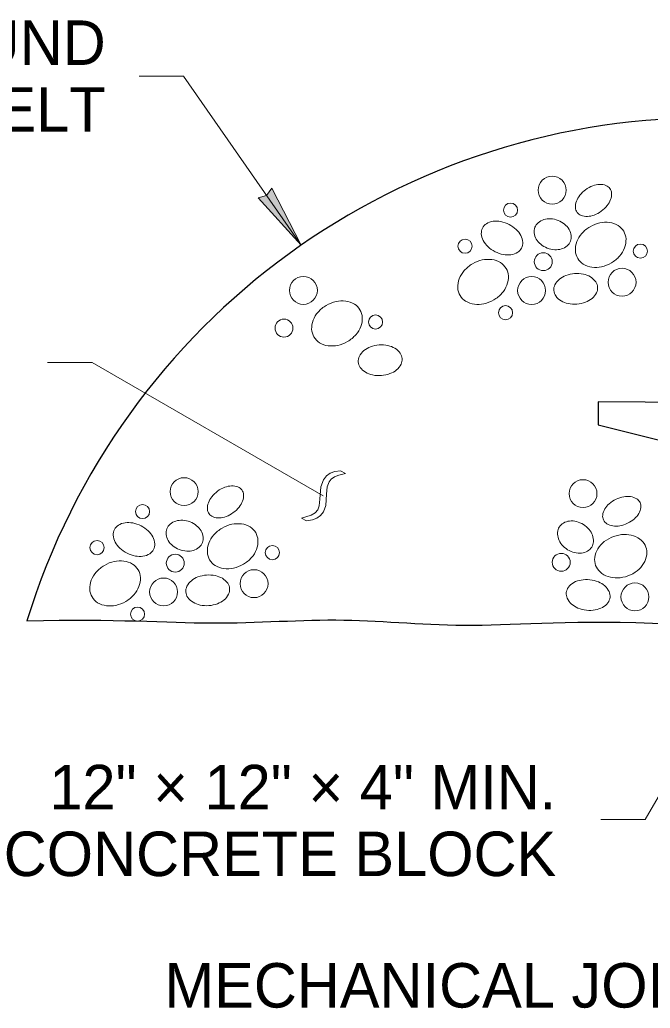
# Model space of a CAD drawing. Extents: x 99860 to 103153, y 99998 to 102077.
# Drawn here: x 100086.3 to 100312.8, y 100201.4 to 100556.8 of the extents above; entities that cross this region are included whole.
import ezdxf
from ezdxf.enums import TextEntityAlignment as Align

# ---------------------------------------------------------------- set-up
doc = ezdxf.new("R2010")
doc.units = 0
doc.header["$LTSCALE"] = 6.4
for name, color, linetype, lineweight in [('1', 7, 'Continuous', 25), ('10', 7, 'Continuous', 13), ('15', 7, 'Continuous', 13), ('18', 7, 'Continuous', 13), ('20', 7, 'Continuous', 13)]:
    doc.layers.add(name, color=color, linetype=linetype, lineweight=lineweight)

msp = doc.modelspace()

# ---------------------------------------------------------------- hatches: boundary and pattern name
at = {"layer": '15'}
msp.add_hatch(color=256, dxfattribs=at).paths.add_polyline_path([(100187.44, 100475.801), (100176.86, 100496.25), (100175.012, 100493.679), (100171.958, 100492.843)])

# ---------------------------------------------------------------- linework, layer by layer
at = {"layer": '1'}
msp.add_arc((100333.435, 100265.78), 255.78, 89.03164, 162.96913, dxfattribs=at)
msp.add_open_spline([(100088.82, 100340.697), (100121.57, 100341.522), (100155.857, 100338.56), (100203.47, 100342.572), (100246.832, 100337.272), (100285.407, 100341.247), (100319.945, 100339.647)], degree=3, dxfattribs=at)
at = {"layer": '10'}
for centre, radius in [((100277.595, 100495.571), 5.019), ((100262.646, 100488.395), 2.537), ((100246.301, 100475.439), 2.537), ((100309.289, 100473.645), 2.537), ((100274.406, 100469.858), 3.22), ((100302.711, 100462.483), 5.019), ((100188.216, 100459.533), 5.019), ((100270.22, 100459.493), 5.019), ((100214.129, 100448.171), 2.537), ((100260.852, 100451.52), 2.537), ((100181.24, 100445.979), 3.22), ((100145.361, 100387.177), 5.019), ((100288.686, 100386.459), 5.019), ((100130.411, 100380.002), 2.537), ((100114.066, 100367.045), 2.537), ((100177.054, 100365.251), 2.537), ((100142.171, 100361.464), 3.22), ((100280.856, 100361.761), 3.22), ((100170.476, 100354.089), 5.019), ((100137.985, 100351.099), 5.019), ((100307.338, 100349.341), 5.019), ((100128.617, 100343.126), 2.537)]:
    msp.add_circle(centre, radius, dxfattribs=at)
for centre, radius, start, end in [((100296.119, 100486.842), 11.024, 110.84431, 126.08477), ((100294.986, 100489.819), 7.839, 92.74951, 110.84431), ((100294.875, 100492.14), 5.515, 68.28483, 92.74951), ((100295.724, 100494.273), 3.219, 36.08477, 68.28483), ((100293.633, 100488.833), 7.839, 141.32523, 159.42002), ((100296.119, 100486.842), 11.024, 126.08477, 141.32523), ((100295.724, 100494.273), 3.219, 3.88471, 36.08477), ((100293.434, 100494.117), 5.515, 339.42002, 3.88471), ((100291.457, 100489.65), 5.515, 159.42002, 183.88471), ((100288.771, 100496.925), 11.024, 306.08477, 321.32523), ((100291.258, 100494.934), 7.839, 321.32523, 339.42002), ((100289.167, 100489.494), 3.219, 183.88471, 216.08477), ((100289.167, 100489.494), 3.219, 216.08477, 248.28483), ((100290.016, 100491.627), 5.515, 248.28483, 272.74951), ((100289.905, 100493.948), 7.839, 272.74951, 290.84431), ((100288.771, 100496.925), 11.024, 290.84431, 306.08477), ((100256.057, 100480.174), 3.917, 122.21424, 152.88878), ((100257.24, 100478.296), 6.137, 97.81622, 122.21424), ((100257.538, 100476.131), 8.322, 79.02152, 97.81622), ((100256.976, 100473.239), 11.268, 62.88878, 79.02152), ((100256.976, 100473.239), 11.268, 46.75604, 62.88878), ((100275.335, 100480.685), 4.207, 130.69622, 158.66336), ((100276.274, 100479.593), 5.648, 106.62121, 130.69622), ((100276.659, 100478.303), 6.994, 86.57049, 106.62121), ((100276.554, 100476.549), 8.751, 68.66336, 86.57049), ((100276.554, 100476.549), 8.751, 50.75623, 68.66336), ((100277.666, 100477.91), 6.994, 30.70551, 50.75623), ((100297.407, 100471.922), 12.202, 102.54735, 120.55568), ((100296.885, 100474.268), 9.798, 82.43038, 102.54735), ((100297.128, 100476.098), 7.952, 58.38014, 82.43038), ((100298.167, 100477.785), 5.971, 30.55568, 58.38014), ((100256.057, 100480.174), 3.917, 152.88878, 183.56332), ((100258.273, 100480.312), 6.137, 183.56332, 207.96135), ((100258.995, 100475.385), 8.322, 27.96135, 46.75604), ((100260.925, 100476.409), 6.137, 3.56332, 27.96135), ((100275.335, 100480.685), 4.207, 158.66336, 186.63049), ((100276.766, 100480.852), 5.648, 186.63049, 210.70551), ((100278.823, 100478.597), 5.648, 6.63049, 30.70551), ((100280.255, 100478.764), 4.207, 338.66336, 6.63049), ((100295.605, 100473.513), 9.798, 138.56401, 158.68099), ((100297.407, 100471.922), 12.202, 120.55568, 138.56401), ((100298.167, 100477.785), 5.971, 2.73122, 30.55568), ((100260.203, 100481.337), 8.322, 207.96135, 226.75604), ((100263.141, 100476.547), 3.917, 332.88878, 3.56332), ((100277.924, 100481.539), 6.994, 210.70551, 230.75623), ((100279.035, 100482.9), 8.751, 230.75623, 248.66336), ((100279.315, 100479.856), 5.648, 286.62121, 310.69623), ((100280.255, 100478.764), 4.207, 310.69623, 338.66336), ((100293.885, 100474.184), 7.952, 158.68099, 182.73122), ((100296.188, 100477.691), 7.952, 338.68099, 2.73122), ((100262.221, 100483.483), 11.268, 226.75604, 242.88878), ((100262.221, 100483.483), 11.268, 242.88878, 259.02152), ((100261.66, 100480.591), 8.322, 259.02152, 277.81622), ((100261.957, 100478.426), 6.137, 277.81622, 302.21424), ((100263.141, 100476.547), 3.917, 302.21424, 332.88878), ((100279.035, 100482.9), 8.751, 248.66336, 266.57049), ((100278.93, 100481.146), 6.994, 266.57049, 286.62121), ((100291.906, 100474.089), 5.971, 182.73122, 210.55568), ((100292.666, 100479.953), 12.202, 300.55568, 318.56401), ((100294.468, 100478.362), 9.798, 318.56401, 338.68099), ((100255.15, 100458.567), 12.202, 120.55568, 138.56401), ((100255.15, 100458.567), 12.202, 102.54735, 120.55568), ((100254.627, 100460.913), 9.798, 82.43038, 102.54735), ((100254.871, 100462.743), 7.952, 58.38014, 82.43038), ((100255.909, 100464.431), 5.971, 30.55568, 58.38014), ((100291.906, 100474.089), 5.971, 210.55568, 238.38014), ((100292.945, 100475.776), 7.952, 238.38014, 262.43038), ((100292.666, 100479.953), 12.202, 282.54735, 300.55568), ((100253.347, 100460.158), 9.798, 138.56401, 158.68099), ((100255.909, 100464.431), 5.971, 2.73122, 30.55568), ((100285.472, 100457.113), 8.322, 110.47593, 129.27062), ((100286.503, 100454.353), 11.268, 94.34319, 110.47593), ((100286.503, 100454.353), 11.268, 78.21045, 94.34319), ((100287.105, 100457.237), 8.322, 59.41576, 78.21045), ((100293.188, 100477.607), 9.798, 262.43038, 282.54735), ((100251.628, 100460.829), 7.952, 158.68099, 182.73122), ((100252.21, 100465.007), 9.798, 318.56401, 338.68099), ((100253.93, 100464.336), 7.952, 338.68099, 2.73122), ((100282.099, 100459.79), 3.917, 153.66865, 184.34319), ((100284.089, 100458.805), 6.137, 129.27062, 153.66865), ((100288.216, 100459.118), 6.137, 35.01773, 59.41576), ((100290.035, 100460.392), 3.917, 4.34319, 35.01773), ((100249.649, 100460.734), 5.971, 182.73122, 210.55568), ((100249.649, 100460.734), 5.971, 210.55568, 238.38014), ((100250.408, 100466.598), 12.202, 300.55568, 318.56401), ((100282.099, 100459.79), 3.917, 184.34319, 215.01773), ((100288.045, 100461.377), 6.137, 309.27062, 333.66865), ((100290.035, 100460.392), 3.917, 333.66865, 4.34319), ((100202.646, 100443.657), 12.202, 120.55568, 138.56401), ((100202.646, 100443.657), 12.202, 102.54735, 120.55568), ((100202.124, 100446.004), 9.798, 82.43038, 102.54735), ((100202.367, 100447.834), 7.952, 58.38014, 82.43038), ((100203.406, 100449.521), 5.971, 30.55568, 58.38014), ((100250.687, 100462.422), 7.952, 238.38014, 262.43038), ((100250.93, 100464.252), 9.798, 262.43038, 282.54735), ((100250.408, 100466.598), 12.202, 282.54735, 300.55568), ((100283.917, 100461.064), 6.137, 215.01773, 239.41576), ((100285.029, 100462.945), 8.322, 239.41576, 258.21045), ((100285.631, 100465.829), 11.268, 258.21045, 274.34319), ((100285.631, 100465.829), 11.268, 274.34319, 290.47593), ((100286.662, 100463.069), 8.322, 290.47593, 309.27062), ((100200.844, 100445.248), 9.798, 138.56401, 158.68099), ((100203.406, 100449.521), 5.971, 2.73122, 30.55568), ((100199.124, 100445.919), 7.952, 158.68099, 182.73122), ((100201.427, 100449.427), 7.952, 338.68099, 2.73122), ((100197.145, 100445.825), 5.971, 182.73122, 210.55568), ((100197.905, 100451.689), 12.202, 300.55568, 318.56401), ((100199.707, 100450.098), 9.798, 318.56401, 338.68099), ((100197.145, 100445.825), 5.971, 210.55568, 238.38014), ((100198.184, 100447.512), 7.952, 238.38014, 262.43038), ((100197.905, 100451.689), 12.202, 282.54735, 300.55568), ((100216.259, 100428.68), 11.268, 94.34319, 110.47593), ((100216.259, 100428.68), 11.268, 78.21045, 94.34319), ((100198.427, 100449.342), 9.798, 262.43038, 282.54735), ((100213.845, 100433.132), 6.137, 129.27062, 153.66865), ((100215.229, 100431.44), 8.322, 110.47593, 129.27062), ((100216.861, 100431.564), 8.322, 59.41576, 78.21045), ((100217.973, 100433.445), 6.137, 35.01773, 59.41576), ((100219.791, 100434.719), 3.917, 4.34319, 35.01773), ((100211.856, 100434.116), 3.917, 153.66865, 184.34319), ((100211.856, 100434.116), 3.917, 184.34319, 215.01773), ((100217.801, 100435.704), 6.137, 309.27062, 333.66865), ((100219.791, 100434.719), 3.917, 333.66865, 4.34319), ((100213.674, 100435.39), 6.137, 215.01773, 239.41576), ((100214.786, 100437.271), 8.322, 239.41576, 258.21045), ((100215.388, 100440.156), 11.268, 274.34319, 290.47593), ((100216.418, 100437.395), 8.322, 290.47593, 309.27062), ((100215.388, 100440.156), 11.268, 258.21045, 274.34319), ((100163.885, 100378.449), 11.024, 126.08477, 141.32523), ((100163.885, 100378.449), 11.024, 110.84431, 126.08477), ((100162.751, 100381.425), 7.839, 92.74951, 110.84431), ((100162.64, 100383.746), 5.515, 68.28483, 92.74951), ((100163.489, 100385.879), 3.219, 36.08477, 68.28483), ((100163.489, 100385.879), 3.219, 3.88471, 36.08477), ((100159.222, 100381.256), 5.515, 159.42002, 183.88471), ((100161.398, 100380.439), 7.839, 141.32523, 159.42002), ((100159.023, 100386.541), 7.839, 321.32523, 339.42002), ((100161.199, 100385.724), 5.515, 339.42002, 3.88471), ((100305.305, 100374.495), 11.024, 115.5641, 130.80456), ((100305.305, 100374.495), 11.024, 100.32364, 115.5641), ((100304.735, 100377.628), 7.839, 82.22884, 100.32364), ((100305.049, 100379.931), 5.515, 57.76416, 82.22884), ((100306.273, 100381.873), 3.219, 25.5641, 57.76416), ((100306.273, 100381.873), 3.219, 353.36404, 25.5641), ((100156.932, 100381.1), 3.219, 183.88471, 216.08477), ((100156.537, 100388.531), 11.024, 290.84431, 306.08477), ((100156.537, 100388.531), 11.024, 306.08477, 321.32523), ((100301.234, 100378.106), 5.515, 148.89935, 173.36404), ((100303.224, 100376.906), 7.839, 130.80456, 148.89936), ((100303.993, 100382.138), 5.515, 328.89935, 353.36404), ((100125.006, 100369.902), 6.137, 97.81622, 122.21424), ((100125.303, 100367.737), 8.322, 79.02152, 97.81622), ((100124.742, 100364.845), 11.268, 62.88878, 79.02152), ((100144.04, 100371.199), 5.648, 106.62121, 130.69622), ((100144.425, 100369.909), 6.994, 86.57049, 106.62121), ((100144.32, 100368.156), 8.751, 68.66336, 86.57049), ((100144.32, 100368.156), 8.751, 50.75623, 68.66336), ((100156.932, 100381.1), 3.219, 216.08477, 248.28483), ((100157.781, 100383.233), 5.515, 248.28483, 272.74951), ((100157.67, 100385.555), 7.839, 272.74951, 290.84431), ((100284.47, 100370.991), 5.648, 96.10054, 120.17556), ((100284.613, 100369.652), 6.994, 76.04982, 96.10054), ((100284.19, 100367.947), 8.751, 58.14269, 76.04982), ((100298.954, 100378.372), 3.219, 173.36404, 205.5641), ((100298.954, 100378.372), 3.219, 205.5641, 237.76416), ((100299.922, 100385.749), 11.024, 295.5641, 310.80456), ((100302.003, 100383.339), 7.839, 310.80456, 328.89936), ((100123.822, 100371.78), 3.917, 152.88878, 183.56332), ((100123.822, 100371.78), 3.917, 122.21424, 152.88878), ((100124.742, 100364.845), 11.268, 46.75604, 62.88878), ((100126.76, 100366.991), 8.322, 27.96135, 46.75604), ((100143.1, 100372.292), 4.207, 158.66336, 186.63049), ((100143.1, 100372.292), 4.207, 130.69622, 158.66336), ((100145.431, 100369.516), 6.994, 30.70551, 50.75623), ((100146.589, 100370.204), 5.648, 6.63049, 30.70551), ((100165.173, 100363.528), 12.202, 120.55568, 138.56401), ((100165.173, 100363.528), 12.202, 102.54735, 120.55568), ((100164.65, 100365.874), 9.798, 82.43038, 102.54735), ((100164.894, 100367.704), 7.952, 58.38014, 82.43038), ((100165.932, 100369.392), 5.971, 30.55568, 58.38014), ((100165.932, 100369.392), 5.971, 2.73122, 30.55568), ((100285.184, 100372.139), 5.648, 176.10983, 200.18484), ((100283.746, 100372.237), 4.207, 148.14269, 176.10982), ((100283.746, 100372.237), 4.207, 120.17556, 148.14269), ((100284.19, 100367.947), 8.751, 40.23556, 58.14269), ((100285.531, 100369.082), 6.994, 20.18484, 40.23556), ((100300.178, 100380.313), 5.515, 237.76416, 262.22884), ((100300.493, 100382.616), 7.839, 262.22884, 280.32364), ((100299.922, 100385.749), 11.024, 280.32364, 295.5641), ((100126.038, 100371.918), 6.137, 183.56332, 207.96135), ((100127.968, 100372.943), 8.322, 207.96135, 226.75604), ((100128.69, 100368.016), 6.137, 3.56332, 27.96135), ((100144.531, 100372.458), 5.648, 186.63049, 210.70551), ((100145.689, 100373.146), 6.994, 210.70551, 230.75623), ((100148.02, 100370.37), 4.207, 310.69623, 338.66336), ((100148.02, 100370.37), 4.207, 338.66336, 6.63049), ((100163.37, 100365.119), 9.798, 138.56401, 158.68099), ((100163.953, 100369.297), 7.952, 338.68099, 2.73122), ((100286.447, 100372.604), 6.994, 200.18484, 220.23556), ((100288.232, 100369.449), 4.207, 328.14269, 356.10982), ((100286.795, 100369.547), 5.648, 356.10983, 20.18484), ((100302.366, 100361.483), 9.798, 128.04334, 148.16032), ((100303.847, 100359.59), 12.202, 110.03501, 128.04334), ((100303.847, 100359.59), 12.202, 92.02668, 110.03501), ((100303.762, 100361.992), 9.798, 71.90971, 92.02668), ((100304.336, 100363.747), 7.952, 47.85948, 71.90971), ((100305.665, 100365.216), 5.971, 20.03501, 47.85948), ((100129.986, 100375.089), 11.268, 226.75604, 242.88878), ((100130.906, 100368.154), 3.917, 302.21424, 332.88878), ((100130.906, 100368.154), 3.917, 332.88878, 3.56332), ((100146.8, 100374.506), 8.751, 230.75623, 248.66336), ((100146.8, 100374.506), 8.751, 248.66336, 266.57049), ((100146.695, 100372.753), 6.994, 266.57049, 286.62121), ((100147.08, 100371.462), 5.648, 286.62121, 310.69623), ((100161.651, 100365.79), 7.952, 158.68099, 182.73122), ((100159.671, 100365.696), 5.971, 182.73122, 210.55568), ((100162.233, 100369.968), 9.798, 318.56401, 338.68099), ((100287.788, 100373.738), 8.751, 220.23556, 238.14269), ((100287.788, 100373.738), 8.751, 238.14269, 256.04982), ((100287.365, 100372.033), 6.994, 256.04982, 276.10054), ((100287.508, 100370.695), 5.648, 276.10054, 300.17556), ((100288.232, 100369.449), 4.207, 300.17556, 328.14269), ((100300.797, 100362.457), 7.952, 148.16032, 172.21055), ((100305.665, 100365.216), 5.971, 352.21055, 20.03501), ((100122.915, 100350.173), 12.202, 102.54735, 120.55568), ((100122.393, 100352.52), 9.798, 82.43038, 102.54735), ((100122.636, 100354.35), 7.952, 58.38014, 82.43038), ((100129.986, 100375.089), 11.268, 242.88878, 259.02152), ((100129.425, 100372.197), 8.322, 259.02152, 277.81622), ((100129.723, 100370.032), 6.137, 277.81622, 302.21424), ((100159.671, 100365.696), 5.971, 210.55568, 238.38014), ((100160.431, 100371.559), 12.202, 300.55568, 318.56401), ((100298.834, 100362.726), 5.971, 172.21055, 200.03501), ((100303.702, 100365.485), 7.952, 328.16032, 352.21055), ((100121.113, 100351.764), 9.798, 138.56401, 158.68099), ((100122.915, 100350.173), 12.202, 120.55568, 138.56401), ((100123.675, 100356.037), 5.971, 30.55568, 58.38014), ((100123.675, 100356.037), 5.971, 2.73122, 30.55568), ((100160.71, 100367.383), 7.952, 238.38014, 262.43038), ((100160.953, 100369.213), 9.798, 262.43038, 282.54735), ((100160.431, 100371.559), 12.202, 282.54735, 300.55568), ((100298.834, 100362.726), 5.971, 200.03501, 227.85948), ((100300.164, 100364.195), 7.952, 227.85948, 251.90971), ((100300.652, 100368.352), 12.202, 290.03501, 308.04334), ((100302.133, 100366.459), 9.798, 308.04334, 328.16032), ((100119.393, 100352.435), 7.952, 158.68099, 182.73122), ((100121.696, 100355.942), 7.952, 338.68099, 2.73122), ((100151.854, 100350.411), 6.137, 129.27062, 153.66865), ((100153.237, 100348.719), 8.322, 110.47593, 129.27062), ((100154.268, 100345.959), 11.268, 94.34319, 110.47593), ((100154.268, 100345.959), 11.268, 78.21045, 94.34319), ((100154.87, 100348.843), 8.322, 59.41576, 78.21045), ((100155.982, 100350.724), 6.137, 35.01773, 59.41576), ((100289.409, 100347.21), 8.322, 99.95526, 118.74996), ((100289.918, 100344.308), 11.268, 83.82252, 99.95526), ((100289.918, 100344.308), 11.268, 67.68978, 83.82252), ((100291.036, 100347.034), 8.322, 48.89509, 67.68978), ((100300.737, 100365.95), 9.798, 251.90971, 272.02668), ((100300.652, 100368.352), 12.202, 272.02668, 290.03501), ((100117.414, 100352.341), 5.971, 182.73122, 210.55568), ((100119.976, 100356.614), 9.798, 318.56401, 338.68099), ((100149.864, 100351.396), 3.917, 153.66865, 184.34319), ((100149.864, 100351.396), 3.917, 184.34319, 215.01773), ((100157.8, 100351.998), 3.917, 4.34319, 35.01773), ((100157.8, 100351.998), 3.917, 333.66865, 4.34319), ((100286.581, 100350.457), 3.917, 143.14798, 173.82252), ((100288.358, 100349.125), 6.137, 118.74996, 143.14798), ((100292.473, 100348.68), 6.137, 24.49706, 48.89509), ((100294.493, 100349.601), 3.917, 353.82252, 24.49706), ((100117.414, 100352.341), 5.971, 210.55568, 238.38014), ((100118.173, 100358.204), 12.202, 282.54735, 300.55568), ((100118.173, 100358.204), 12.202, 300.55568, 318.56401), ((100151.683, 100352.67), 6.137, 215.01773, 239.41576), ((100154.427, 100354.675), 8.322, 290.47593, 309.27062), ((100155.81, 100352.983), 6.137, 309.27062, 333.66865), ((100286.581, 100350.457), 3.917, 173.82252, 204.49706), ((100288.601, 100351.378), 6.137, 204.49706, 228.89509), ((100294.493, 100349.601), 3.917, 323.14798, 353.82252), ((100118.453, 100354.028), 7.952, 238.38014, 262.43038), ((100118.696, 100355.858), 9.798, 262.43038, 282.54735), ((100152.794, 100354.551), 8.322, 239.41576, 258.21045), ((100153.396, 100357.435), 11.268, 258.21045, 274.34319), ((100153.396, 100357.435), 11.268, 274.34319, 290.47593), ((100290.038, 100353.024), 8.322, 228.89509, 247.68978), ((100291.156, 100355.75), 11.268, 247.68978, 263.82252), ((100291.156, 100355.75), 11.268, 263.82252, 279.95526), ((100291.666, 100352.848), 8.322, 279.95526, 298.74996), ((100292.717, 100350.932), 6.137, 298.74996, 323.14798)]:
    msp.add_arc(centre, radius, start, end, dxfattribs=at)
at = {"layer": '15'}
for p, q in [((100129.171, 100536.607), (100145.171, 100536.607)), ((100187.44, 100475.801), (100145.171, 100536.607)), ((100096.274, 100433.623), (100112.274, 100433.623)), ((100195.371, 100385.647), (100112.274, 100433.623)), ((100351.694, 100339.647), (100311.069, 100269.283)), ((100295.069, 100269.283), (100311.069, 100269.283))]:
    msp.add_line(p, q, dxfattribs=at)
msp.add_lwpolyline([(100187.44, 100475.801), (100176.86, 100496.25), (100175.012, 100493.679), (100171.958, 100492.843)], close=True, dxfattribs=at)
at = {"layer": '18', "lineweight": 25}
msp.add_lwpolyline([(100327.957, 100419.172), (100294.157, 100419.422), (100294.157, 100411.147), (100342.02, 100399.222), (100342.02, 100385.122)], dxfattribs=at)
at = {"layer": '20'}
msp.add_line((100187.486, 100377.694), (100189.317, 100376.637), dxfattribs=at)
for points in [[(100203.322, 100393.652), (100201.492, 100394.709), (100199.52, 100394.455), (100197.844, 100393.822), (100196.473, 100392.805), (100195.402, 100391.406), (100194.473, 100388.849), (100194.101, 100384.453), (100193.897, 100382.038), (100193.366, 100380.634), (100192.446, 100379.549)], [(100189.317, 100376.638), (100191.433, 100376.999), (100193.092, 100377.643), (100194.394, 100378.601), (100195.397, 100379.926), (100196.291, 100382.224), (100196.555, 100386.306), (100196.781, 100388.848), (100197.413, 100390.66), (100198.235, 100391.71), (100199.333, 100392.515), (100200.953, 100393.136), (100203.322, 100393.653)], [(100192.446, 100379.549), (100191.049, 100378.678), (100187.486, 100377.695)]]:
    msp.add_lwpolyline(points, dxfattribs=at)

# ---------------------------------------------------------------- texts
for s, p in [('15 POUND', (100117.183, 100540.607)), ('ASPHALTIC FELT', (100117.183, 100516.607)), ('12" × 12" × 4" MIN.', (100279.071, 100272.945)), ('CONCRETE BLOCK', (100279.071, 100248.945)), ('MECHANICAL JOINT', (100346.34, 100201.659))]:
    msp.add_text(s, height=16, dxfattribs=at).set_placement(p, align=Align.RIGHT)

doc.saveas('drawing.dxf')
